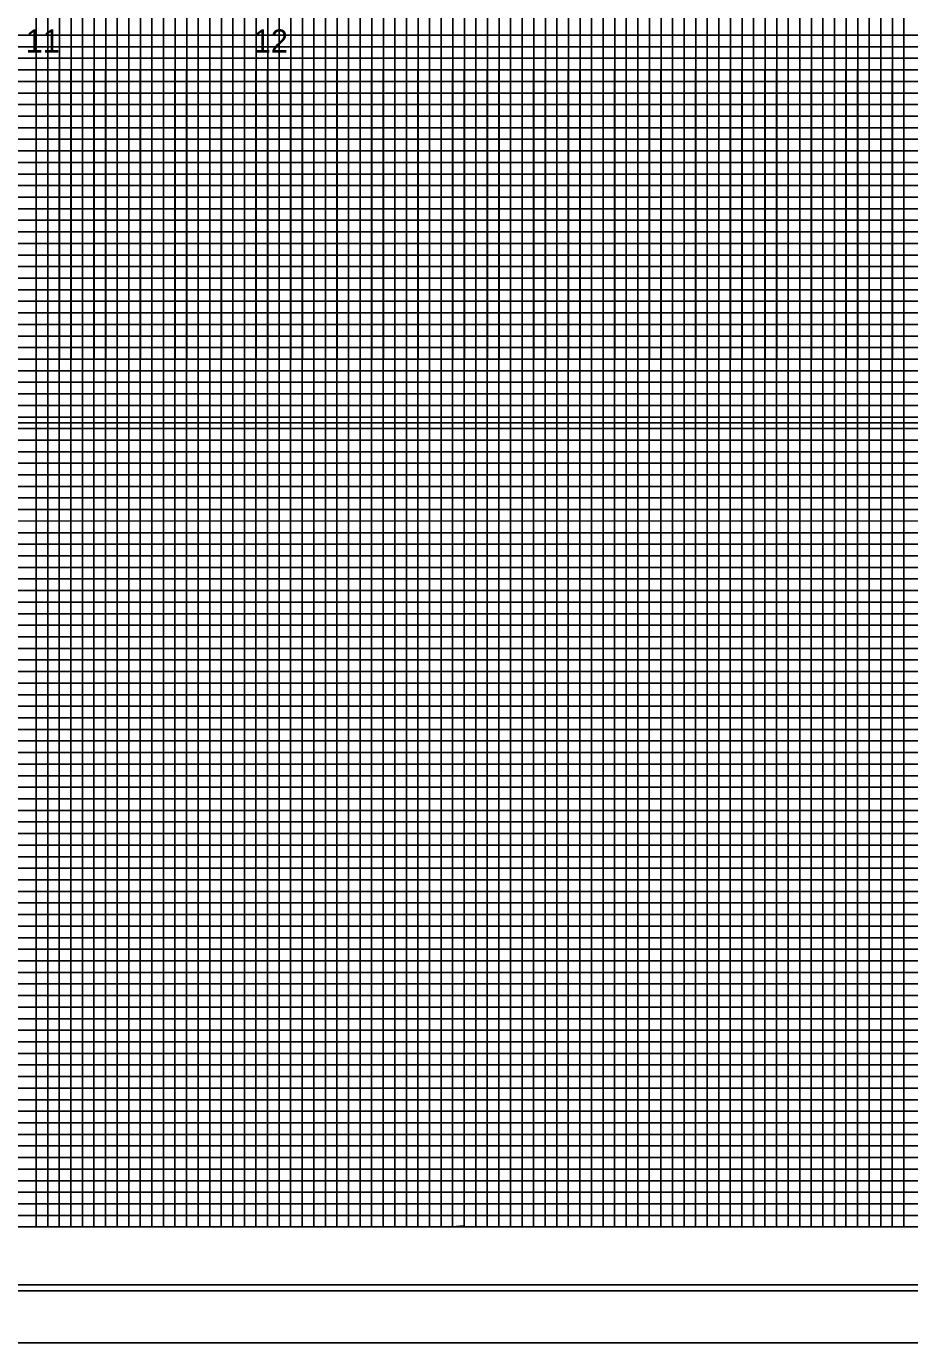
# Model space of a CAD drawing. Extents: x 553912 to 567693, y 512355 to 537539.
# Drawn here: x 566372 to 566754, y 513390 to 513959 of the extents above; entities that cross this region are included whole.
import ezdxf

# ---------------------------------------------------------------- set-up
doc = ezdxf.new("R2010")
doc.units = 0
for name, color, linetype in [('Default', 7, 'Continuous'), ('Exist Vertical Profile Horizontal Axis Label Major', 7, 'Continuous'), ('Old_Level_42', 7, 'Continuous'), ('Old_Level_51', 7, 'Continuous'), ('Old_Level_53', 7, 'Continuous'), ('Old_Level_54', 7, 'Continuous'), ('Prop ROW Permanent Easement CELL', 7, 'Continuous'), ('Sheet Cutting Line CELL', 7, 'Continuous'), ('Sheet DOT Grid CELL', 7, 'Continuous'), ('Sheet Layout Profile Border Port 2', 7, 'Continuous'), ('Sheet Plot Border Inside CELL', 7, 'Continuous'), ('Sheet Plot Border Outside CELL', 7, 'Continuous'), ('Sheet Profile CELL', 7, 'Continuous'), ('Sheet Profile Grid Major CELL', 7, 'Continuous'), ('Sheet Profile Grid Middle CELL', 7, 'Continuous'), ('Sheet Profile Grid Minor CELL', 7, 'Continuous'), ('Sheet Row Area Data CELL', 7, 'Continuous'), ('Sheet Summary Guardrail CELL', 7, 'Continuous')]:
    doc.layers.add(name, color=color, linetype=linetype)

msp = doc.modelspace()

# ---------------------------------------------------------------- linework, layer by layer
at = {"layer": 'Default'}
msp.add_lwpolyline([(567693.42, 514864.71), (566009.42, 514864.71), (566009.42, 513764.71), (567693.42, 513764.71)], close=True, dxfattribs=at)
at = {"layer": 'Old_Level_42'}
for p, q in [((566376.42, 514839.71), (566376.42, 513814.71)), ((566426.42, 514839.71), (566426.42, 513814.71)), ((566476.42, 514839.71), (566476.42, 513814.71)), ((566526.42, 514839.71), (566526.42, 513814.71)), ((566576.42, 514839.71), (566576.42, 513814.71)), ((566626.42, 514839.71), (566626.42, 513814.71)), ((566676.42, 514839.71), (566676.42, 513814.71)), ((566726.42, 514839.71), (566726.42, 513814.71)), ((566176.42, 513914.71), (567676.42, 513914.71)), ((566176.42, 513864.71), (567676.42, 513864.71))]:
    msp.add_line(p, q, dxfattribs=at)
at = {"layer": 'Old_Level_51'}
msp.add_lwpolyline([(567688.92, 514842.26), (566022.42, 514842.26), (566022.42, 513787.16), (567688.92, 513787.16)], close=True, dxfattribs=at)
at = {"layer": 'Old_Level_53'}
msp.add_line((567676.42, 513814.71), (566176.42, 513814.71), dxfattribs=at)
msp.add_lwpolyline([(567676.42, 514839.71), (566176.42, 514839.71), (566176.42, 513789.71), (567676.42, 513789.71)], close=True, dxfattribs=at)
at = {"layer": 'Old_Level_54'}
for points in [[(566176.42, 514839.71), (566226.42, 514839.71), (566226.42, 513814.71), (566276.42, 513814.71), (566276.42, 514839.71), (566326.42, 514839.71), (566326.42, 513814.71), (566376.42, 513814.71), (566376.42, 514839.71), (566426.42, 514839.71), (566426.42, 513814.71), (566476.42, 513814.71), (566476.42, 514839.71), (566526.42, 514839.71), (566526.42, 513814.71), (566576.42, 513814.71), (566576.42, 514839.71), (566626.42, 514839.71), (566626.42, 513814.71), (566676.42, 513814.71), (566676.42, 514839.71), (566726.42, 514839.71), (566726.42, 513814.71), (566776.42, 513814.71)], [(567676.42, 513864.71), (566176.42, 513864.71), (566176.42, 513914.71), (567676.42, 513914.71)]]:
    msp.add_lwpolyline(points, dxfattribs=at)
at = {"layer": 'Prop ROW Permanent Easement CELL'}
for points in [[(566251.42, 513814.71), (566251.42, 514839.71), (566301.42, 514839.71), (566301.42, 513814.71), (566351.42, 513814.71), (566351.42, 514839.71), (566401.42, 514839.71), (566401.42, 513814.71), (566451.42, 513814.71), (566451.42, 514839.71), (566501.42, 514839.71), (566501.42, 513814.71), (566551.42, 513814.71), (566551.42, 514839.71), (566601.42, 514839.71), (566601.42, 513814.71), (566651.42, 513814.71), (566651.42, 514839.71), (566701.42, 514839.71), (566701.42, 513814.71), (566751.42, 513814.71), (566751.42, 514839.71), (566801.42, 514839.71)], [(567676.42, 513939.71), (566176.42, 513939.71), (566176.42, 513889.71), (567676.42, 513889.71)], [(567676.42, 513839.71), (566176.42, 513839.71)]]:
    msp.add_lwpolyline(points, dxfattribs=at)
at = {"layer": 'Sheet Cutting Line CELL'}
msp.add_line((565534.35, 513389.72), (567218.35, 513389.72), dxfattribs=at)
at = {"layer": 'Sheet DOT Grid CELL'}
for p, q in [((565701.35, 513939.72), (567201.24, 513939.72)), ((566401.35, 513939.72), (566401.35, 513439.72)), ((566451.35, 513939.72), (566451.35, 513439.72)), ((566501.35, 513939.72), (566501.35, 513439.72)), ((566551.35, 513939.72), (566551.35, 513439.72)), ((566601.35, 513939.72), (566601.35, 513439.72)), ((566651.35, 513939.72), (566651.35, 513439.72)), ((566701.35, 513939.72), (566701.35, 513439.72)), ((566751.35, 513939.72), (566751.35, 513439.72)), ((565701.35, 513889.72), (567201.24, 513889.72)), ((565701.35, 513839.72), (567201.24, 513839.72)), ((565701.35, 513789.72), (567201.24, 513789.72)), ((565701.35, 513739.72), (567201.24, 513739.72)), ((565701.35, 513689.72), (567201.24, 513689.72)), ((565701.35, 513639.72), (567201.24, 513639.72)), ((565701.35, 513589.72), (567201.24, 513589.72)), ((565701.35, 513539.72), (567201.24, 513539.72)), ((565701.35, 513489.72), (567201.24, 513489.72))]:
    msp.add_line(p, q, dxfattribs=at)
at = {"layer": 'Sheet Layout Profile Border Port 2'}
msp.add_lwpolyline([(565751.35, 513939.72), (567151.35, 513939.72), (567151.35, 513439.72), (565751.35, 513439.72)], close=True, dxfattribs=at)
at = {"layer": 'Sheet Plot Border Inside CELL'}
msp.add_lwpolyline([(565547.35, 513412.17), (567213.85, 513412.17), (567213.85, 514467.27), (565547.35, 514467.27)], close=True, dxfattribs=at)
at = {"layer": 'Sheet Plot Border Outside CELL'}
msp.add_lwpolyline([(565534.35, 513389.72), (567218.35, 513389.72), (567218.35, 514489.72), (565534.35, 514489.72)], close=True, dxfattribs=at)
at = {"layer": 'Sheet Profile CELL'}
for p, q in [((565701.35, 513939.72), (567201.35, 513939.72)), ((567201.35, 513439.72), (565701.35, 513439.72)), ((565701.35, 513414.72), (567201.35, 513414.72))]:
    msp.add_line(p, q, dxfattribs=at)
msp.add_lwpolyline([(567201.35, 514464.72), (565701.35, 514464.72), (565701.35, 513414.72), (567201.35, 513414.72)], close=True, dxfattribs=at)
at = {"layer": 'Sheet Profile Grid Major CELL'}
for p, q in [((566401.35, 513939.72), (566451.35, 513939.72)), ((566501.35, 513939.72), (566551.35, 513939.72)), ((566601.35, 513939.72), (566651.35, 513939.72)), ((566701.35, 513939.72), (566751.35, 513939.72))]:
    msp.add_line(p, q, dxfattribs=at)
for points in [[(566351.35, 513439.72), (566401.35, 513439.72), (566401.35, 513939.72), (566451.35, 513939.72), (566451.35, 513439.72), (566501.35, 513439.72), (566501.35, 513939.72), (566551.35, 513939.72), (566551.35, 513439.72), (566601.35, 513439.72), (566601.35, 513939.72), (566651.35, 513939.72), (566651.35, 513439.72), (566701.35, 513439.72), (566701.35, 513939.72), (566751.35, 513939.72), (566751.35, 513439.72), (566801.35, 513439.72)], [(567201.35, 513889.72), (565701.35, 513889.72)], [(567201.35, 513839.72), (565701.35, 513839.72), (565701.35, 513789.72), (567201.35, 513789.72)], [(567201.35, 513739.72), (565701.35, 513739.72), (565701.35, 513689.72), (567201.35, 513689.72)], [(567201.35, 513639.72), (565701.35, 513639.72), (565701.35, 513589.72), (567201.35, 513589.72)], [(567201.35, 513539.72), (565701.35, 513539.72), (565701.35, 513539.72), (565701.35, 513489.72), (567201.35, 513489.72)], [(567201.35, 513439.72), (565701.35, 513439.72)]]:
    msp.add_lwpolyline(points, dxfattribs=at)
at = {"layer": 'Sheet Profile Grid Middle CELL'}
for points in [[(566326.35, 513939.72), (566376.35, 513939.72), (566376.35, 513439.72), (566426.35, 513439.72), (566426.35, 513939.72), (566476.35, 513939.72), (566476.35, 513439.72), (566526.35, 513439.72), (566526.35, 513939.72), (566576.35, 513939.72), (566576.35, 513439.72), (566626.35, 513439.72), (566626.35, 513939.72), (566676.35, 513939.72), (566676.35, 513439.72), (566726.35, 513439.72), (566726.35, 513939.72), (566776.35, 513939.72)], [(565701.35, 513914.72), (567201.35, 513914.72)], [(567201.35, 513864.72), (565701.35, 513864.72), (565701.35, 513814.72), (567201.35, 513814.72)], [(567201.35, 513764.72), (565701.35, 513764.72), (565701.35, 513714.72), (567201.35, 513714.72)], [(567201.35, 513664.72), (565701.35, 513664.72), (565701.35, 513614.72), (567201.35, 513614.72)], [(567201.35, 513564.72), (565701.35, 513564.72), (565701.35, 513514.72), (567201.35, 513514.72)], [(567201.35, 513464.72), (565701.35, 513464.72)]]:
    msp.add_lwpolyline(points, dxfattribs=at)
at = {"layer": 'Sheet Profile Grid Minor CELL'}
for p, q in [((565751.35, 513934.72), (567151.35, 513934.72)), ((567151.35, 513929.72), (565751.35, 513929.72)), ((565751.35, 513924.72), (567151.35, 513924.72)), ((567151.35, 513919.72), (565751.35, 513919.72)), ((565751.35, 513909.72), (567151.35, 513909.72)), ((567151.35, 513904.72), (565751.35, 513904.72)), ((565751.35, 513899.72), (567151.35, 513899.72)), ((567151.35, 513894.72), (565751.35, 513894.72)), ((565751.35, 513884.72), (567151.35, 513884.72)), ((567151.35, 513879.72), (565751.35, 513879.72)), ((565751.35, 513874.72), (567151.35, 513874.72)), ((567151.35, 513869.72), (565751.35, 513869.72)), ((565751.35, 513859.72), (567151.35, 513859.72)), ((567151.35, 513854.72), (565751.35, 513854.72)), ((565751.35, 513849.72), (567151.35, 513849.72)), ((567151.35, 513844.72), (565751.35, 513844.72)), ((565751.35, 513834.72), (567151.35, 513834.72)), ((567151.35, 513829.72), (565751.35, 513829.72)), ((565751.35, 513824.72), (567151.35, 513824.72)), ((567151.35, 513819.72), (565751.35, 513819.72)), ((565751.35, 513809.72), (567151.35, 513809.72)), ((567151.35, 513804.72), (565751.35, 513804.72)), ((565751.35, 513799.72), (567151.35, 513799.72)), ((567151.35, 513794.72), (565751.35, 513794.72)), ((565751.35, 513784.72), (567151.35, 513784.72)), ((567151.35, 513779.72), (565751.35, 513779.72)), ((565751.35, 513774.72), (567151.35, 513774.72)), ((567151.35, 513769.72), (565751.35, 513769.72)), ((565751.35, 513759.72), (567151.35, 513759.72)), ((567151.35, 513754.72), (565751.35, 513754.72)), ((565751.35, 513749.72), (567151.35, 513749.72)), ((567151.35, 513744.72), (565751.35, 513744.87)), ((565751.35, 513734.72), (567151.35, 513734.72)), ((567151.35, 513729.72), (565751.35, 513729.72)), ((565751.35, 513724.72), (567151.35, 513724.72)), ((567151.35, 513719.72), (565751.35, 513719.72)), ((565751.35, 513709.72), (567151.35, 513709.72)), ((567151.35, 513704.72), (565751.35, 513704.72)), ((565751.35, 513699.72), (567151.35, 513699.72)), ((567151.35, 513694.72), (565751.35, 513694.72)), ((565751.35, 513684.72), (567151.35, 513684.72)), ((567151.35, 513679.72), (565751.35, 513679.72)), ((565751.35, 513674.72), (567151.35, 513674.72)), ((567151.35, 513669.72), (565751.35, 513669.72)), ((565751.35, 513659.72), (567151.35, 513659.72)), ((567151.35, 513654.72), (565751.35, 513654.72)), ((565751.35, 513649.72), (567151.35, 513649.72)), ((567151.35, 513644.72), (565751.35, 513644.72)), ((565751.35, 513634.72), (567151.35, 513634.72)), ((567151.35, 513629.72), (565751.35, 513629.72)), ((565751.35, 513624.72), (567151.35, 513624.72)), ((567151.35, 513619.72), (565751.35, 513619.72)), ((565751.35, 513609.72), (567151.35, 513609.72)), ((567151.35, 513604.72), (565751.35, 513604.72)), ((565751.35, 513599.72), (567151.35, 513599.72)), ((567151.35, 513594.72), (565751.35, 513594.72)), ((565751.35, 513584.72), (567151.35, 513584.72)), ((567151.35, 513579.72), (565751.35, 513579.72)), ((565751.35, 513574.72), (567151.35, 513574.72)), ((567151.35, 513569.72), (565751.35, 513569.72)), ((565751.35, 513559.72), (567151.35, 513559.72)), ((567151.35, 513554.72), (565751.35, 513554.72)), ((565751.35, 513549.72), (567151.35, 513549.72)), ((567151.35, 513544.72), (565751.35, 513544.72)), ((565751.35, 513534.72), (567151.35, 513534.72)), ((567151.35, 513529.72), (565751.35, 513529.72)), ((565751.35, 513524.72), (567151.35, 513524.72)), ((567151.35, 513519.72), (565751.35, 513519.72)), ((565751.35, 513509.72), (567151.35, 513509.72)), ((567151.35, 513504.72), (565751.35, 513504.72)), ((565751.35, 513499.72), (567151.35, 513499.72)), ((567151.35, 513494.72), (565751.35, 513494.72)), ((565751.35, 513484.72), (567151.35, 513484.72)), ((567151.35, 513479.72), (565751.35, 513479.72)), ((565751.35, 513474.72), (567151.35, 513474.72)), ((567151.35, 513469.72), (565751.35, 513469.72)), ((565751.35, 513459.72), (567151.35, 513459.72)), ((567151.35, 513454.72), (565751.35, 513454.72)), ((565751.35, 513449.72), (567151.35, 513449.72)), ((565751.35, 513444.72), (567151.35, 513444.72))]:
    msp.add_line(p, q, dxfattribs=at)
for points in [[(566371.35, 513939.72), (566381.35, 513939.72), (566381.35, 513439.72), (566386.35, 513439.72), (566386.35, 513939.72), (566391.35, 513939.72), (566391.35, 513439.72), (566396.35, 513439.72), (566396.35, 513939.72), (566406.35, 513939.72), (566406.35, 513439.72), (566406.35, 513439.72), (566411.35, 513439.72), (566411.35, 513939.72), (566416.35, 513939.72), (566416.35, 513439.72), (566421.35, 513439.72), (566421.35, 513939.72), (566431.35, 513939.72), (566431.35, 513439.72), (566436.35, 513439.72), (566436.35, 513939.72), (566441.35, 513939.72), (566441.35, 513439.72), (566446.35, 513439.72), (566446.35, 513939.72), (566456.35, 513939.72), (566456.35, 513439.72), (566461.35, 513439.72), (566461.35, 513939.72), (566466.35, 513939.72), (566466.35, 513439.72), (566471.35, 513439.72), (566471.35, 513939.72), (566481.35, 513939.72), (566481.35, 513439.72), (566486.35, 513439.72), (566486.35, 513939.72), (566491.35, 513939.72), (566491.35, 513439.72), (566496.35, 513439.72), (566496.35, 513939.72), (566506.35, 513939.72), (566506.35, 513439.72), (566511.35, 513439.72), (566511.35, 513939.72), (566516.35, 513939.72), (566516.35, 513439.72), (566521.35, 513439.72), (566521.35, 513939.72), (566531.35, 513939.72), (566531.35, 513439.72), (566536.35, 513439.72), (566536.35, 513939.72), (566541.35, 513939.72), (566541.35, 513439.72), (566546.35, 513439.72), (566546.35, 513939.72), (566556.35, 513939.72), (566556.35, 513439.72), (566561.05, 513440.27), (566561.35, 513439.72), (566561.35, 513939.72), (566566.35, 513939.72), (566566.35, 513439.72), (566571.35, 513439.72), (566571.35, 513939.72), (566581.35, 513939.72), (566581.35, 513439.72), (566586.35, 513439.72)], [(566586.35, 513439.72), (566586.35, 513939.72), (566591.35, 513939.72), (566591.35, 513439.72), (566596.35, 513439.72), (566596.35, 513939.72), (566606.35, 513939.72), (566606.35, 513439.72), (566611.35, 513439.72), (566611.35, 513939.72), (566616.35, 513939.72), (566616.35, 513439.72), (566621.35, 513439.72), (566621.35, 513939.72), (566631.35, 513939.72), (566631.35, 513439.72), (566636.35, 513439.72), (566636.35, 513939.72), (566641.35, 513939.72), (566641.35, 513439.72), (566646.35, 513439.72), (566646.35, 513939.72), (566656.35, 513939.72), (566656.35, 513439.72), (566661.35, 513439.72), (566661.35, 513939.72), (566666.35, 513939.72), (566666.35, 513439.72), (566671.35, 513439.72), (566671.35, 513939.72), (566681.35, 513939.72), (566681.35, 513439.72), (566686.35, 513439.72), (566686.35, 513939.72), (566691.35, 513939.72), (566691.35, 513439.72), (566696.35, 513439.72), (566696.35, 513939.72), (566706.35, 513939.72), (566706.35, 513439.72), (566711.35, 513439.72), (566711.35, 513939.72), (566716.35, 513939.72), (566716.35, 513439.72), (566721.35, 513439.72), (566721.35, 513939.72), (566731.35, 513939.72), (566731.35, 513439.72), (566736.35, 513439.72), (566736.35, 513939.72), (566741.35, 513939.72), (566741.35, 513439.72), (566746.35, 513439.72), (566746.35, 513939.72), (566756.35, 513939.72)]]:
    msp.add_lwpolyline(points, dxfattribs=at)
at = {"layer": 'Sheet Row Area Data CELL'}
msp.add_line((566009.42, 513764.71), (567693.42, 513764.71), dxfattribs=at)
at = {"layer": 'Sheet Summary Guardrail CELL'}
for points in [[(566381.42, 514839.71), (566381.42, 513814.71), (566386.42, 513814.71), (566386.42, 514839.71)], [(566391.42, 513814.71), (566396.42, 513814.71), (566396.42, 514839.71)], [(566391.42, 514839.71), (566391.42, 513814.71)], [(566406.42, 514839.71), (566406.42, 513814.71), (566411.42, 513814.71), (566411.42, 514839.71)], [(566416.42, 514839.71), (566416.42, 513814.71), (566421.42, 513814.71), (566421.42, 514839.71)], [(566431.42, 514839.71), (566431.42, 513814.71), (566436.42, 513814.71), (566436.42, 514839.71)], [(566441.42, 514839.71), (566441.42, 513814.71), (566446.42, 513814.71), (566446.42, 514839.71)], [(566456.42, 514839.71), (566456.42, 513814.71), (566461.42, 513814.71), (566461.42, 514839.71)], [(566466.42, 514839.71), (566466.42, 513814.71), (566471.42, 513814.71), (566471.42, 514839.71)], [(566481.42, 514839.71), (566481.42, 513814.71), (566486.42, 513814.71), (566486.42, 514839.71)], [(566491.42, 514839.71), (566491.42, 513814.71), (566496.42, 513814.71), (566496.42, 514839.71)], [(566506.42, 514839.71), (566506.42, 513814.71), (566511.42, 513814.71), (566511.42, 514839.71)], [(566516.42, 514839.71), (566516.42, 513814.71), (566521.42, 513814.71), (566521.42, 514839.71)], [(566531.42, 514839.71), (566531.42, 513814.71), (566536.42, 513814.71), (566536.42, 514839.71)], [(566541.42, 514839.71), (566541.42, 513814.71), (566546.42, 513814.71), (566546.42, 514839.71)], [(566556.42, 514839.71), (566556.42, 513814.71), (566571.42, 513814.71), (566571.42, 514839.71)], [(566561.42, 514839.71), (566561.42, 513814.71), (566566.42, 513814.71), (566566.42, 514839.71)], [(566581.42, 514839.71), (566581.42, 513814.71), (566586.42, 513814.71), (566586.42, 514839.71)], [(566591.42, 514839.71), (566591.42, 513814.71), (566596.42, 513814.71), (566596.42, 514839.71)], [(566606.42, 514839.71), (566606.42, 513814.71), (566611.42, 513814.71), (566611.42, 514839.71)], [(566616.42, 514839.71), (566616.42, 513814.71), (566621.42, 513814.71), (566621.42, 514839.71)], [(566631.42, 514839.71), (566631.42, 513814.71), (566636.42, 513814.71), (566636.42, 514839.71)], [(566641.42, 514839.71), (566641.42, 513814.71), (566646.42, 513814.71), (566646.42, 514839.71)], [(566656.42, 514839.71), (566656.42, 513814.71), (566661.42, 513814.71), (566661.42, 514839.71)], [(566666.42, 514839.71), (566666.42, 513814.71), (566671.42, 513814.71), (566671.42, 514839.71)], [(566681.42, 514839.71), (566681.42, 513814.71), (566686.42, 513814.71), (566686.42, 514839.71)], [(566691.42, 514839.71), (566691.42, 513814.71), (566696.42, 513814.71), (566696.42, 514839.71)], [(566706.42, 514839.71), (566706.42, 513814.71)], [(566711.42, 514839.71), (566711.42, 513814.71), (566716.42, 513814.71), (566716.42, 514839.71), (566721.42, 514839.71), (566721.42, 513814.71), (566731.42, 513814.71), (566731.42, 514839.71), (566736.42, 514839.71), (566736.42, 513814.71), (566741.42, 513814.71), (566741.42, 514839.71), (566746.42, 514839.71), (566746.42, 513814.71)], [(566561.42, 514839.11), (566561.42, 513814.71), (566566.42, 513814.71), (566566.42, 514839.11)], [(567626.42, 513954.71), (566226.42, 513954.71), (566226.42, 513949.71), (567626.42, 513949.71)], [(567626.42, 513944.71), (566226.42, 513944.71), (566226.42, 513934.71), (567626.42, 513934.71)], [(567626.42, 513929.71), (566226.42, 513929.71), (566226.42, 513924.71), (567626.42, 513924.71)], [(567626.42, 513919.71), (566226.42, 513919.71), (566226.42, 513909.71), (567626.42, 513909.71)], [(567626.42, 513904.71), (566226.42, 513904.71), (566226.42, 513899.71), (567626.42, 513899.71)], [(567626.42, 513894.71), (566226.42, 513894.71), (566226.42, 513884.71), (567626.42, 513884.71)], [(567626.42, 513879.71), (566226.42, 513879.71), (566226.42, 513874.71), (567626.42, 513874.71)], [(567626.42, 513869.71), (566226.42, 513869.71), (566226.42, 513859.71), (567626.42, 513859.71)], [(567626.42, 513854.71), (566226.42, 513854.71), (566226.42, 513849.71), (567626.42, 513849.71)], [(567626.42, 513844.71), (566226.42, 513844.71), (566226.42, 513834.71), (567626.42, 513834.71)], [(567626.42, 513829.71), (566226.42, 513829.71), (566226.42, 513824.71), (567626.42, 513824.71)], [(567626.42, 513819.71), (566226.42, 513819.71)]]:
    msp.add_lwpolyline(points, dxfattribs=at)

# ---------------------------------------------------------------- texts
at = {"layer": 'Exist Vertical Profile Horizontal Axis Label Major'}
for s, p in [('11', (566371.78, 513947.22)), ('12', (566470.33, 513947.22))]:
    msp.add_text(s, height=10, dxfattribs=at).set_placement(p)

doc.saveas('drawing.dxf')
